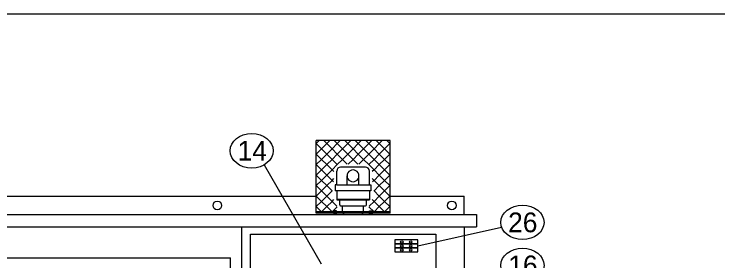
# Model space of a CAD drawing. Extents: x 99862 to 103680, y 99470 to 105076.
# Drawn here: x 102012 to 102582, y 104875 to 105076 of the extents above; entities that cross this region are included whole.
import ezdxf

# ---------------------------------------------------------------- set-up
doc = ezdxf.new("R2010")
doc.units = 0
for name, color, linetype in [('Level 1', 7, 'Continuous'), ('Level 15', 7, 'Continuous'), ('Level 20', 7, 'Continuous'), ('Level 40', 7, 'Continuous')]:
    doc.layers.add(name, color=color, linetype=linetype)

msp = doc.modelspace()

# ---------------------------------------------------------------- linework, layer by layer
at = {"layer": 'Level 1'}
for p, q in [((102256.66, 104915.18), (102256.66, 104972.94)), ((102316.66, 104972.94), (102256.66, 104972.94)), ((102256.88, 104970.49), (102259.34, 104972.94)), ((102262.94, 104972.94), (102265.39, 104970.49)), ((102267.84, 104972.94), (102265.39, 104970.49)), ((102273.9, 104970.49), (102271.45, 104972.94)), ((102276.35, 104972.94), (102273.9, 104970.49)), ((102282.41, 104970.49), (102279.96, 104972.94)), ((102284.86, 104972.94), (102282.41, 104970.49)), ((102290.92, 104970.49), (102288.46, 104972.94)), ((102293.37, 104972.94), (102290.92, 104970.49)), ((102299.42, 104970.49), (102296.97, 104972.94)), ((102301.88, 104972.94), (102299.42, 104970.49)), ((102305.48, 104972.94), (102307.93, 104970.49)), ((102307.93, 104970.49), (102310.39, 104972.94)), ((102316.44, 104970.49), (102313.99, 104972.94)), ((102316.66, 104915.18), (102316.66, 104972.94)), ((102256.66, 104970.71), (102256.88, 104970.49)), ((102256.88, 104970.49), (102256.66, 104970.26)), ((102261.14, 104966.23), (102256.88, 104970.49)), ((102256.88, 104961.98), (102261.14, 104966.23)), ((102265.39, 104970.49), (102261.14, 104966.23)), ((102261.14, 104966.23), (102265.39, 104961.98)), ((102265.39, 104970.49), (102269.65, 104966.23)), ((102269.65, 104966.23), (102265.39, 104961.98)), ((102269.65, 104966.23), (102273.9, 104970.49)), ((102273.9, 104961.98), (102269.65, 104966.23)), ((102273.9, 104970.49), (102278.15, 104966.23)), ((102278.15, 104966.23), (102273.9, 104961.98)), ((102278.15, 104966.23), (102282.41, 104970.49)), ((102282.41, 104961.98), (102278.15, 104966.23)), ((102282.41, 104970.49), (102286.66, 104966.23)), ((102286.66, 104966.23), (102282.41, 104961.98)), ((102286.66, 104966.23), (102290.92, 104970.49)), ((102290.92, 104961.98), (102286.66, 104966.23)), ((102290.92, 104970.49), (102295.17, 104966.23)), ((102295.17, 104966.23), (102290.92, 104961.98)), ((102295.17, 104966.23), (102299.42, 104970.49)), ((102299.42, 104961.98), (102295.17, 104966.23)), ((102299.42, 104970.49), (102303.68, 104966.23)), ((102303.68, 104966.23), (102299.42, 104961.98)), ((102303.68, 104966.23), (102307.93, 104970.49)), ((102307.93, 104961.98), (102303.68, 104966.23)), ((102307.93, 104970.49), (102312.19, 104966.23)), ((102312.19, 104966.23), (102307.93, 104961.98)), ((102312.19, 104966.23), (102316.44, 104970.49)), ((102316.44, 104961.98), (102312.19, 104966.23)), ((102316.66, 104970.71), (102316.44, 104970.49)), ((102316.44, 104970.49), (102316.66, 104970.27)), ((102256.66, 104962.2), (102256.88, 104961.98)), ((102256.88, 104961.98), (102256.66, 104961.76)), ((102261.14, 104957.72), (102256.88, 104961.98)), ((102265.39, 104961.98), (102261.14, 104957.72)), ((102265.39, 104961.98), (102269.65, 104957.72)), ((102269.65, 104957.72), (102273.9, 104961.98)), ((102273.9, 104961.98), (102278.15, 104957.72)), ((102278.15, 104957.72), (102282.41, 104961.98)), ((102282.41, 104961.98), (102286.66, 104957.72)), ((102286.66, 104957.72), (102290.92, 104961.98)), ((102290.92, 104961.98), (102295.17, 104957.72)), ((102295.17, 104957.72), (102299.42, 104961.98)), ((102299.42, 104961.98), (102303.68, 104957.72)), ((102303.68, 104957.72), (102307.93, 104961.98)), ((102307.93, 104961.98), (102312.19, 104957.72)), ((102312.19, 104957.72), (102316.44, 104961.98)), ((102316.66, 104962.2), (102316.44, 104961.98)), ((102316.44, 104961.98), (102316.66, 104961.76)), ((102256.88, 104953.47), (102261.14, 104957.72)), ((102261.14, 104957.72), (102265.39, 104953.47)), ((102269.65, 104957.72), (102265.39, 104953.47)), ((102273.9, 104953.47), (102269.65, 104957.72)), ((102278.15, 104957.72), (102273.9, 104953.47)), ((102282.03, 104953.85), (102278.15, 104957.72)), ((102286.66, 104957.72), (102282.79, 104953.85)), ((102290.54, 104953.85), (102286.66, 104957.72)), ((102295.17, 104957.72), (102291.3, 104953.85)), ((102299.42, 104953.47), (102295.17, 104957.72)), ((102303.68, 104957.72), (102299.42, 104953.47)), ((102307.93, 104953.47), (102303.68, 104957.72)), ((102312.19, 104957.72), (102307.93, 104953.47)), ((102316.44, 104953.47), (102312.19, 104957.72)), ((102256.66, 104953.69), (102256.88, 104953.47)), ((102256.88, 104953.47), (102256.66, 104953.25)), ((102261.14, 104949.22), (102256.88, 104953.47)), ((102256.88, 104944.96), (102261.14, 104949.22)), ((102265.39, 104953.47), (102261.14, 104949.22)), ((102261.14, 104949.22), (102265.39, 104944.96)), ((102265.39, 104953.47), (102269.65, 104949.22)), ((102269.65, 104949.22), (102265.39, 104944.96)), ((102269.65, 104949.22), (102273.9, 104953.47)), ((102271.02, 104947.84), (102269.65, 104949.22)), ((102273.9, 104953.47), (102274.12, 104953.25)), ((102296.69, 104951.44), (102276.63, 104951.44)), ((102299.21, 104953.25), (102299.42, 104953.47)), ((102299.42, 104953.47), (102303.68, 104949.22)), ((102303.68, 104949.22), (102302.3, 104947.84)), ((102303.68, 104949.22), (102307.93, 104953.47)), ((102307.93, 104944.96), (102303.68, 104949.22)), ((102307.93, 104953.47), (102312.19, 104949.22)), ((102312.19, 104949.22), (102307.93, 104944.96)), ((102312.19, 104949.22), (102316.44, 104953.47)), ((102316.44, 104944.96), (102312.19, 104949.22)), ((102316.66, 104953.69), (102316.44, 104953.47)), ((102316.44, 104953.47), (102316.66, 104953.25)), ((102256.66, 104945.18), (102256.88, 104944.96)), ((102256.88, 104944.96), (102256.66, 104944.74)), ((102261.14, 104940.71), (102256.88, 104944.96)), ((102265.39, 104944.96), (102261.14, 104940.71)), ((102265.39, 104944.96), (102269.65, 104940.71)), ((102273.43, 104937), (102273.43, 104948.23)), ((102281.85, 104937), (102281.85, 104944.38)), ((102291.47, 104937), (102291.47, 104944.38)), ((102299.9, 104937), (102299.9, 104948.23)), ((102303.68, 104940.71), (102307.93, 104944.96)), ((102307.93, 104944.96), (102312.19, 104940.71)), ((102312.19, 104940.71), (102316.44, 104944.96)), ((102316.66, 104945.18), (102316.44, 104944.96)), ((102316.44, 104944.96), (102316.66, 104944.74)), ((102256.88, 104936.45), (102261.14, 104940.71)), ((102261.14, 104940.71), (102265.39, 104936.45)), ((102269.65, 104940.71), (102265.39, 104936.45)), ((102269.65, 104940.71), (102271.02, 104942.08)), ((102270.94, 104939.41), (102269.65, 104940.71)), ((102302.3, 104942.08), (102303.68, 104940.71)), ((102303.68, 104940.71), (102302.38, 104939.41)), ((102307.93, 104936.45), (102303.68, 104940.71)), ((102312.19, 104940.71), (102307.93, 104936.45)), ((102316.44, 104936.45), (102312.19, 104940.71)), ((102256.66, 104936.67), (102256.88, 104936.45)), ((102256.88, 104936.45), (102256.66, 104936.23)), ((102261.14, 104932.2), (102256.88, 104936.45)), ((102256.88, 104927.94), (102261.14, 104932.2)), ((102265.39, 104936.45), (102261.14, 104932.2)), ((102261.14, 104932.2), (102265.39, 104927.94)), ((102265.39, 104936.45), (102269.65, 104932.2)), ((102269.65, 104932.2), (102265.39, 104927.94)), ((102269.65, 104932.2), (102269.82, 104932.37)), ((102269.82, 104932.03), (102269.65, 104932.2)), ((102273.43, 104937), (102272.22, 104937)), ((102272.22, 104937), (102272.22, 104932.19)), ((102301.1, 104932.19), (102272.22, 104932.19)), ((102273.43, 104937), (102299.9, 104937)), ((102273.43, 104932.19), (102273.43, 104924.97)), ((102299.9, 104937), (102301.1, 104937)), ((102299.9, 104932.19), (102299.9, 104924.97)), ((102301.1, 104937), (102301.1, 104932.19)), ((102303.51, 104932.37), (102303.68, 104932.2)), ((102303.68, 104932.2), (102303.51, 104932.03)), ((102303.68, 104932.2), (102307.93, 104936.45)), ((102307.93, 104927.94), (102303.68, 104932.2)), ((102307.93, 104936.45), (102312.19, 104932.2)), ((102312.19, 104932.2), (102307.93, 104927.94)), ((102312.19, 104932.2), (102316.44, 104936.45)), ((102316.44, 104927.94), (102312.19, 104932.2)), ((102316.66, 104936.67), (102316.44, 104936.45)), ((102316.44, 104936.45), (102316.66, 104936.23)), ((102256.66, 104928.17), (102256.88, 104927.94)), ((102256.88, 104927.94), (102256.66, 104927.72)), ((102261.14, 104923.69), (102256.88, 104927.94)), ((102265.39, 104927.94), (102261.14, 104923.69)), ((102265.39, 104927.94), (102269.65, 104923.69)), ((102303.68, 104923.69), (102307.93, 104927.94)), ((102307.93, 104927.94), (102312.19, 104923.69)), ((102312.19, 104923.69), (102316.44, 104927.94)), ((102316.66, 104928.16), (102316.44, 104927.94)), ((102316.44, 104927.94), (102316.66, 104927.72)), ((102256.88, 104919.44), (102261.14, 104923.69)), ((102261.14, 104923.69), (102265.39, 104919.44)), ((102269.65, 104923.69), (102265.39, 104919.44)), ((102269.65, 104923.69), (102271.02, 104925.06)), ((102273.61, 104919.73), (102269.65, 104923.69)), ((102273.43, 104925.57), (102299.9, 104925.57)), ((102273.43, 104924.97), (102299.9, 104924.97)), ((102275.83, 104920.76), (102275.83, 104924.97)), ((102276.43, 104920.16), (102296.89, 104920.16)), ((102278.24, 104915.35), (102278.24, 104920.16)), ((102295.08, 104915.35), (102295.08, 104920.16)), ((102297.49, 104920.76), (102297.49, 104924.97)), ((102303.68, 104923.69), (102299.71, 104919.73)), ((102302.3, 104925.07), (102303.68, 104923.69)), ((102307.93, 104919.44), (102303.68, 104923.69)), ((102312.19, 104923.69), (102307.93, 104919.44)), ((102316.44, 104919.44), (102312.19, 104923.69)), ((102256.66, 104919.66), (102256.88, 104919.44)), ((102256.88, 104919.44), (102256.66, 104919.21)), ((102316.66, 104915.18), (102256.66, 104915.18)), ((102256.66, 104914.14), (102256.66, 104915.08)), ((102316.66, 104915.08), (102256.66, 104915.08)), ((102261.14, 104915.18), (102256.88, 104919.44)), ((102265.39, 104919.44), (102261.14, 104915.18)), ((102265.39, 104919.44), (102269.65, 104915.18)), ((102269.65, 104915.18), (102273.79, 104919.33)), ((102299.53, 104919.33), (102303.68, 104915.18)), ((102303.68, 104915.18), (102307.93, 104919.44)), ((102307.93, 104919.44), (102312.19, 104915.18)), ((102312.19, 104915.18), (102316.44, 104919.44)), ((102316.66, 104919.66), (102316.44, 104919.44)), ((102316.44, 104919.44), (102316.66, 104919.22)), ((102316.66, 104914.14), (102316.66, 104915.08)), ((102316.66, 104914.14), (102256.66, 104914.14)), ((102280.65, 104912.94), (102292.68, 104912.94)), ((102203.66, 104897.04), (102353.66, 104897.04)), ((102203.66, 104537.04), (102203.66, 104897.04)), ((102353.66, 104897.04), (102353.66, 104537.04)), ((101985.88, 104877.94), (102187.44, 104877.94)), ((102187.44, 104547.94), (102187.44, 104877.94))]:
    msp.add_line(p, q, dxfattribs=at)
for points in [[(99862, 102999.5), (103151, 102999.5), (103151, 105075.5), (99862, 105075.5)], [(102320.45, 104889.16), (102339.23, 104889.16), (102339.23, 104892.39), (102320.45, 104892.39)], [(102320.45, 104885.93), (102339.23, 104885.93), (102339.23, 104889.16), (102320.45, 104889.16)], [(102320.45, 104882.7), (102339.23, 104882.7), (102339.23, 104885.93), (102320.45, 104885.93)]]:
    msp.add_lwpolyline(points, close=True, dxfattribs=at)
for centre in [(102326.26, 104890.77), (102333.41, 104890.77), (102326.26, 104887.55), (102333.41, 104887.55), (102326.26, 104884.32), (102333.41, 104884.32)]:
    msp.add_circle(centre, 1.03, dxfattribs=at)
for centre, radius, start, end in [((102276.63, 104948.23), 3.21, 90, 180), ((102286.66, 104944.38), 4.81, 359.9997, 180), ((102296.69, 104948.23), 3.21, 0, 90), ((102286.66, 104944.38), 4.81, 180, 0.0003), ((102276.43, 104920.76), 0.602, 180, 270), ((102296.89, 104920.76), 0.602, 270, 0), ((102280.65, 104915.35), 2.41, 180, 270), ((102292.68, 104915.35), 2.41, 270, 0)]:
    msp.add_arc(centre, radius, start, end, dxfattribs=at)
at = {"layer": 'Level 15'}
for p, q in [((102214.75, 104953.33), (102260.87, 104873.04)), ((101966.66, 104912.94), (102386.66, 104912.94)), ((102386.66, 104912.94), (102386.66, 104902.94)), ((101966.66, 104902.94), (102386.66, 104902.94)), ((102339.23, 104887.55), (102407.13, 104902.84))]:
    msp.add_line(p, q, dxfattribs=at)
for centre in [(102176.66, 104920.44), (102366.66, 104920.44)]:
    msp.add_circle(centre, 3.5, dxfattribs=at)
at = {"layer": 'Level 20'}
for centre in [(102204.55, 104964.7), (102423.98, 104906.64), (102423.98, 104871.78)]:
    msp.add_ellipse(centre, major_axis=(-17.5, 0), ratio=0.8, dxfattribs=at)
at = {"layer": 'Level 40'}
for p, q in [((101976.66, 104927.94), (102256.66, 104927.94)), ((102316.66, 104927.94), (102376.66, 104927.94)), ((102376.66, 104912.94), (102376.66, 104927.94)), ((101976.66, 104912.94), (102376.66, 104912.94)), ((102196.66, 104512.94), (102196.66, 104902.94)), ((102376.66, 104902.94), (102376.66, 104497.94))]:
    msp.add_line(p, q, dxfattribs=at)
for points in [[(102273.21, 104915.1), (102273.21, 104915.88), (102271.24, 104915.88), (102271.24, 104915.1)], [(102300.12, 104915.1), (102300.12, 104915.88), (102302.08, 104915.88), (102302.08, 104915.1)], [(102273.57, 104913.18), (102273.57, 104912.94), (102270.88, 104912.94), (102270.88, 104913.18)], [(102273.54, 104913.35), (102273.54, 104913.18), (102270.91, 104913.18), (102270.91, 104913.35)], [(102273.21, 104913.35), (102273.21, 104914.14), (102271.24, 104914.14), (102271.24, 104913.35)], [(102299.76, 104913.18), (102299.76, 104912.94), (102302.44, 104912.94), (102302.44, 104913.18)], [(102299.79, 104913.35), (102299.79, 104913.18), (102302.41, 104913.18), (102302.41, 104913.35)], [(102300.12, 104913.35), (102300.12, 104914.14), (102302.08, 104914.14), (102302.08, 104913.35)]]:
    msp.add_lwpolyline(points, close=True, dxfattribs=at)

# ---------------------------------------------------------------- texts
at = {"layer": 'Level 20'}
for s, p in [('14', (102193.07, 104956.7)), ('26', (102412.35, 104898.64)), ('16', (102412.5, 104863.78))]:
    msp.add_text(s, height=16, dxfattribs=at).set_placement(p)

doc.saveas('drawing.dxf')
